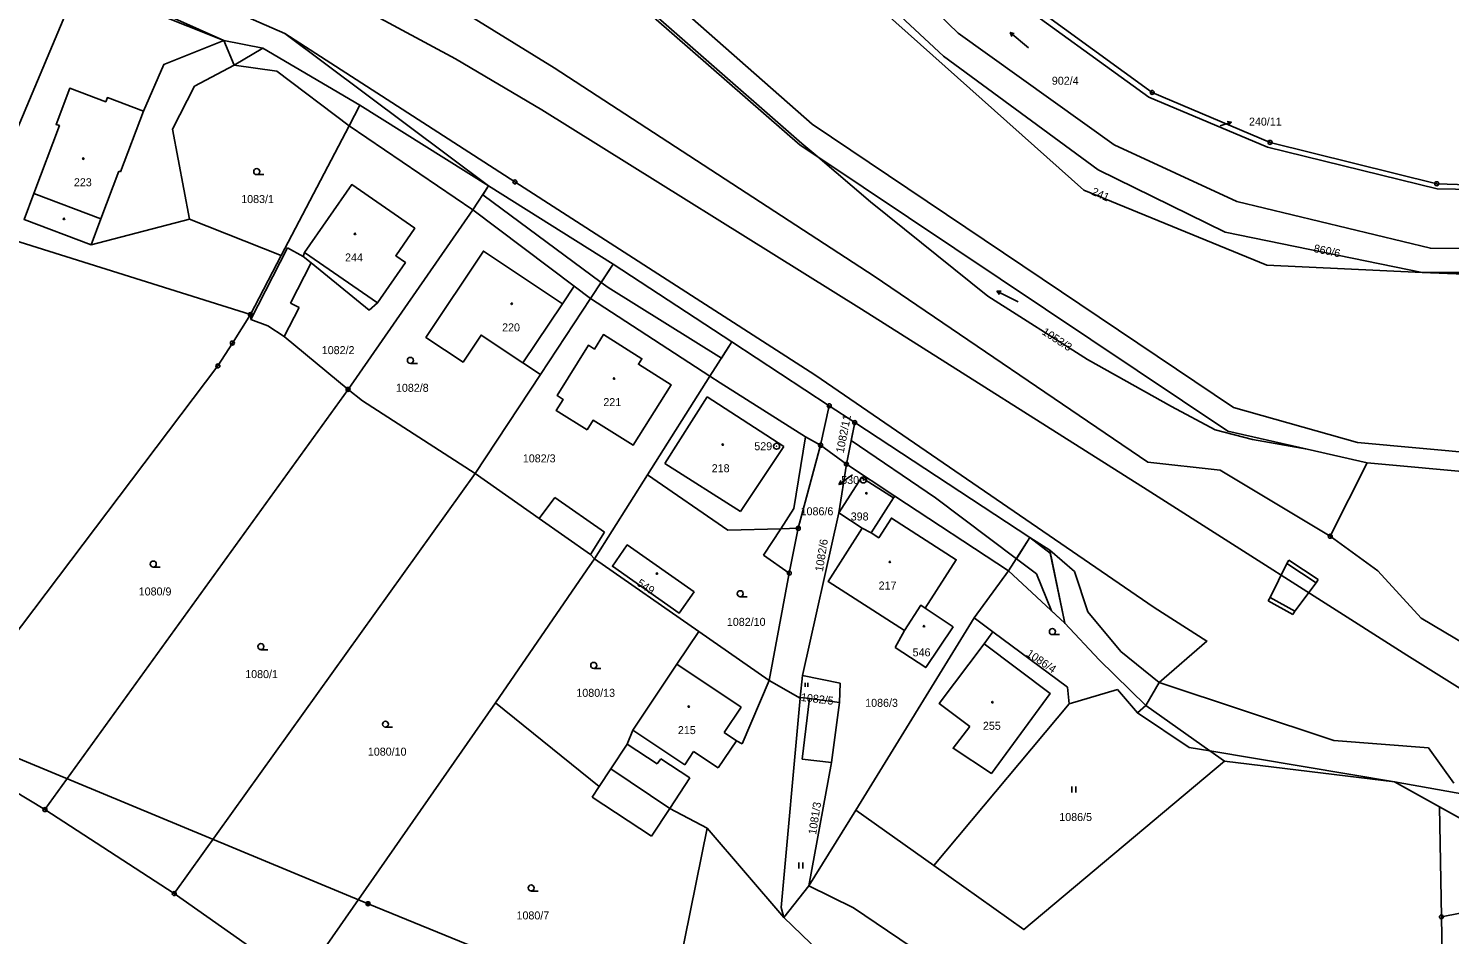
# Model space of a CAD drawing. Extents: x -745926 to -742978, y -968282 to -965689.
# Drawn here: x -744856.3 to -744678.7, y -967259 to -967145.7 of the extents above; entities that cross this region are included whole.
import ezdxf

# ---------------------------------------------------------------- set-up
doc = ezdxf.new("R2010")
doc.units = 0
for name, color, linetype in [('Hranice parcel', 7, 'Continuous'), ('Parcelní čísla', 7, 'Continuous'), ('Pop  PČ popisy', 7, 'Continuous'), ('Poz předměty', 7, 'Continuous'), ('Vnitřní kresba', 7, 'Continuous'), ('Věcná břemena k části', 7, 'Continuous'), ('Značky bodu BP', 7, 'Continuous'), ('Značky budov', 7, 'Continuous'), ('Značky kultur', 7, 'Continuous')]:
    doc.layers.add(name, color=color, linetype=linetype)

msp = doc.modelspace()

# ---------------------------------------------------------------- linework, layer by layer
at = {"layer": 'Hranice parcel'}
for p, q in [((-744862.95, -967170.69), (-744849.99, -967139.99)), ((-744849.99, -967139.99), (-744831.9, -967147.24)), ((-744826.99, -967148.18), (-744831.9, -967147.24)), ((-744814.88, -967155.32), (-744826.99, -967148.18)), ((-744798.8, -967165.4), (-744814.88, -967155.32)), ((-744757.65, -967161.79), (-744759.62, -967160.12)), ((-744783.22, -967175.19), (-744798.8, -967165.4)), ((-744828.56, -967181.48), (-744862.95, -967170.69)), ((-744783.22, -967175.19), (-744786.06, -967179.49)), ((-744768.4, -967184.9), (-744783.22, -967175.19)), ((-744643.72, -967176.24), (-744682.11, -967176.24)), ((-744658.4, -967177.18), (-744682.11, -967176.24)), ((-744792.32, -967188.99), (-744786.06, -967179.49)), ((-744830.81, -967185.04), (-744828.56, -967181.48)), ((-744832.63, -967187.9), (-744830.81, -967185.04)), ((-744756.21, -967192.89), (-744768.4, -967184.9)), ((-744868.17, -967234.92), (-744832.63, -967187.9)), ((-744792.32, -967188.99), (-744800.48, -967201.36)), ((-744816.36, -967190.83), (-744854.24, -967243.36)), ((-744757.29, -967197.82), (-744756.21, -967192.89)), ((-744756.21, -967192.89), (-744753.03, -967194.98)), ((-744753.03, -967194.98), (-744754.06, -967200.19)), ((-744731.13, -967209.33), (-744753.03, -967194.98)), ((-744760.08, -967208.2), (-744757.29, -967197.82)), ((-744754.06, -967200.19), (-744757.29, -967197.82)), ((-744689, -967200), (-744696.48, -967198.31)), ((-744689, -967200), (-744693.6, -967209.2)), ((-744838.08, -967253.85), (-744800.48, -967201.36)), ((-744785.57, -967212.01), (-744778.91, -967201.5)), ((-744755.02, -967206.28), (-744754.06, -967200.19)), ((-744750.99, -967208.76), (-744748.18, -967204.39)), ((-744759.57, -967226.6), (-744755.02, -967206.28)), ((-744755.02, -967206.28), (-744752.08, -967208.16)), ((-744750.99, -967208.76), (-744752.08, -967208.16)), ((-744728.66, -967210.94), (-744731.13, -967209.33)), ((-744772.53, -967221.09), (-744785.57, -967212.01)), ((-744744.22, -967218.17), (-744740.72, -967220.51)), ((-744763.73, -967227.22), (-744772.53, -967221.09)), ((-744747.96, -967223.11), (-744746.8, -967220.96)), ((-744716.65, -967230.33), (-744722.47, -967224.64)), ((-744759.57, -967226.6), (-744759.84, -967229.33)), ((-744759.86, -967229.43), (-744763.73, -967227.22)), ((-744797.92, -967229.99), (-744822.28, -967264.93)), ((-744759.84, -967229.33), (-744759.86, -967229.43)), ((-744854.24, -967243.36), (-744868.17, -967234.92)), ((-744706.83, -967237.32), (-744685.57, -967239.87)), ((-744685.57, -967239.87), (-744679.95, -967243.01)), ((-744854.24, -967243.36), (-744838.08, -967253.85)), ((-744752.9, -967243.41), (-744758.77, -967252.9)), ((-744743.14, -967250.35), (-744752.9, -967243.41)), ((-744679.95, -967243.01), (-744679.7, -967256.76)), ((-744777.66, -967276.07), (-744771.46, -967245.67)), ((-744771.46, -967245.67), (-744761.9, -967256.85)), ((-744758.77, -967252.9), (-744761.9, -967256.85)), ((-744822.28, -967264.93), (-744838.08, -967253.85))]:
    msp.add_line(p, q, dxfattribs=at)
for points in [[(-744693.6, -967209.2), (-744707.34, -967200.94), (-744716.41, -967199.92), (-744750.6, -967176.7), (-744790.58, -967150.66), (-744800.6, -967144.47), (-744829.49, -967128.26), (-744860.55, -967111.29), (-744889.69, -967099.44), (-744913.09, -967089.29)], [(-744949.24, -967094.01), (-744923.2, -967101.49), (-744908.83, -967109.73), (-744904.12, -967111.71), (-744867.87, -967127.34), (-744824.27, -967146.35), (-744795.5, -967164.9), (-744758, -967189), (-744715.6, -967218.1), (-744709, -967222.3), (-744714.96, -967227.46), (-744716.65, -967230.33)], [(-744831.9, -967147.24), (-744886.96, -967122.64), (-744909.4, -967113.93), (-744920.02, -967107.58), (-744947.9, -967099.97)], [(-744682.11, -967176.24), (-744706.73, -967171.2), (-744722.61, -967163.39), (-744741.92, -967149.18), (-744762.18, -967130.32), (-744771.51, -967120.53), (-744792.07, -967099.84)], [(-744792.07, -967099.84), (-744773.3, -967122.27), (-744724.39, -967165.93), (-744701.53, -967175.32), (-744682.11, -967176.24)], [(-744761.31, -967116.64), (-744753.2, -967122.59), (-744734.47, -967141.12), (-744716.27, -967154.3), (-744701.42, -967160.58), (-744680.25, -967165.77), (-744652.66, -967166.26), (-744623.32, -967164.11), (-744567.41, -967157.02), (-744564.47, -967157.4)], [(-744806.72, -967119.21), (-744782.44, -967140.57), (-744759.86, -967160.31), (-744757.65, -967161.79)], [(-744759.62, -967160.12), (-744785.56, -967137.39), (-744806.27, -967119.19)], [(-744752.98, -967122.18), (-744734.28, -967140.31), (-744715.85, -967153.73), (-744701.12, -967159.96), (-744680.29, -967165.13), (-744652.93, -967166.02), (-744624.12, -967163.47), (-744567.4, -967156.72)], [(-744758.97, -967128.01), (-744740.08, -967146.3), (-744720.61, -967160.28), (-744705.28, -967167.36), (-744681.07, -967173.2), (-744652.2, -967173.45), (-744630.58, -967172.14)], [(-744831.9, -967147.24), (-744839.39, -967150.22), (-744841.94, -967156.05), (-744846.44, -967154.36), (-744846.63, -967154.88), (-744851.14, -967153.19), (-744852.85, -967157.72), (-744852.43, -967157.87), (-744855.62, -967166.35), (-744856.85, -967169.61), (-744848.47, -967172.76), (-744836.16, -967169.58), (-744838.29, -967158.3), (-744835.56, -967152.95), (-744830.59, -967150.33), (-744826.99, -967148.18)], [(-744814.88, -967155.32), (-744816.22, -967157.89), (-744824.7, -967174.1), (-744828.56, -967181.48)], [(-744696.48, -967198.31), (-744703.32, -967197.09), (-744707.99, -967195.9), (-744713.45, -967192.99), (-744723.92, -967187.09), (-744736.41, -967179.17), (-744751.06, -967167.39), (-744757.65, -967161.79)], [(-744696.48, -967198.31), (-744706.4, -967196.07), (-744757.65, -967161.79)], [(-744813.73, -967180.92), (-744812.67, -967180.02), (-744809.18, -967174.98), (-744810.39, -967174.14), (-744808.01, -967170.69), (-744815.9, -967165.23), (-744821.78, -967173.72), (-744821.98, -967174.24), (-744820.97, -967175.03), (-744813.73, -967180.92)], [(-744816.36, -967190.83), (-744800.75, -967168.4), (-744798.8, -967165.4)], [(-744786.06, -967179.49), (-744788.1, -967177.95), (-744789.57, -967180.14), (-744799.44, -967173.56), (-744806.62, -967184.34), (-744801.98, -967187.43), (-744799.72, -967184.04), (-744794.49, -967187.52), (-744792.32, -967188.99)], [(-744816.36, -967190.83), (-744824.32, -967184.23), (-744826.37, -967182.9), (-744828.49, -967182.1), (-744828.56, -967181.48)], [(-744786.47, -967195.9), (-744785.72, -967194.7), (-744780.73, -967197.82), (-744775.99, -967190.26), (-744780.07, -967187.7), (-744779.63, -967187), (-744784.43, -967183.99), (-744785.56, -967185.8), (-744786.31, -967185.33), (-744790.24, -967191.6), (-744789.47, -967192.09), (-744790.34, -967193.48), (-744786.47, -967195.9)], [(-744768.4, -967184.9), (-744771.12, -967189.2), (-744778.91, -967201.5)], [(-744800.48, -967201.36), (-744814.56, -967192.27), (-744816.36, -967190.83)], [(-744617.81, -967196.99), (-744645.44, -967199.78), (-744674.83, -967201.29), (-744689, -967200)], [(-744785.57, -967212.01), (-744786.07, -967211.48), (-744792.46, -967206.98), (-744800.48, -967201.36)], [(-744778.91, -967201.5), (-744768.87, -967208.41), (-744762.27, -967208.26), (-744760.08, -967208.2)], [(-744748.18, -967204.39), (-744752.17, -967201.83), (-744755.02, -967206.28)], [(-744754.06, -967200.19), (-744748.01, -967204.17), (-744748.18, -967204.39)], [(-744744.22, -967218.17), (-744740.34, -967212.13), (-744748.45, -967206.93), (-744750.03, -967209.38), (-744750.99, -967208.76)], [(-744760.08, -967208.2), (-744761.21, -967213.8), (-744763.73, -967227.22)], [(-744752.08, -967208.16), (-744756.36, -967214.83), (-744746.8, -967220.96)], [(-744773.1, -967216.14), (-744774.96, -967218.79), (-744783.32, -967212.94), (-744781.46, -967210.28), (-744773.1, -967216.14)], [(-744752.9, -967243.41), (-744738.08, -967219.39), (-744733.79, -967213.53), (-744731.13, -967209.33)], [(-744654.82, -967235.73), (-744682.24, -967219.41), (-744687.64, -967213.53), (-744693.6, -967209.2)], [(-744797.92, -967229.99), (-744786.52, -967213.4), (-744785.57, -967212.01)], [(-744722.47, -967224.64), (-744726.77, -967220.07), (-744728.66, -967210.94)], [(-744746.8, -967220.96), (-744744.78, -967217.81), (-744744.22, -967218.17)], [(-744772.53, -967221.09), (-744775.26, -967225.16), (-744780.77, -967233.41), (-744781.46, -967235.16), (-744783.51, -967238.27)], [(-744740.72, -967220.51), (-744744.16, -967225.61), (-744747.96, -967223.11)], [(-744738.66, -967232.96), (-744740.73, -967235.69), (-744735.94, -967238.83), (-744728.62, -967228.84), (-744736.85, -967222.62), (-744742.48, -967230.08), (-744738.66, -967232.96)], [(-744754.94, -967229.97), (-744754.86, -967227.57), (-744759.57, -967226.6)], [(-744743.14, -967250.35), (-744726.24, -967230.14), (-744720.2, -967228.36), (-744717.69, -967231.25), (-744716.65, -967230.33)], [(-744783.51, -967238.27), (-744784.96, -967240.45), (-744797.92, -967229.99)], [(-744761.9, -967256.85), (-744762.21, -967255.57), (-744759.86, -967229.43)], [(-744754.94, -967229.97), (-744758.7, -967229.48), (-744759.84, -967229.33)], [(-744758.77, -967252.9), (-744755.92, -967237.48), (-744754.94, -967229.97)], [(-744716.65, -967230.33), (-744708.66, -967236.02), (-744706.83, -967237.32)], [(-744706.83, -967237.32), (-744731.9, -967258.34), (-744743.14, -967250.35)], [(-744783.51, -967238.27), (-744776.13, -967243.2), (-744771.46, -967245.67)], [(-744685.57, -967239.87), (-744674.82, -967241.79), (-744668.23, -967242.96), (-744659.62, -967250.35)], [(-744679.7, -967256.76), (-744670.98, -967255.03), (-744664.34, -967251.69), (-744660.58, -967250.82), (-744659.62, -967250.35)], [(-744738.76, -967274.28), (-744743.16, -967262.41), (-744753.18, -967255.64), (-744758.77, -967252.9)], [(-744749.3, -967268.65), (-744751.81, -967266.56), (-744761.9, -967256.85)], [(-744679.47, -967286.02), (-744679.22, -967283.47), (-744679.7, -967256.76)]]:
    msp.add_lwpolyline(points, dxfattribs=at)
at = {"layer": 'Pop  PČ popisy'}
for p, q in [((-744707.35, -967157.88), (-744705.92, -967157.44)), ((-744705.92, -967157.44), (-744706.47, -967157.35)), ((-744705.92, -967157.44), (-744706.32, -967157.83)), ((-744753.79, -967201.86), (-744755.02, -967202.72)), ((-744753.32, -967201.52), (-744753.79, -967201.86)), ((-744755.02, -967202.72), (-744754.75, -967202.23)), ((-744755.02, -967202.72), (-744754.47, -967202.64))]:
    msp.add_line(p, q, dxfattribs=at)
at = {"layer": 'Poz předměty'}
for p, q in [((-744832.7, -967133.45), (-744802.93, -967149.54)), ((-744802.93, -967149.54), (-744792.15, -967155.89)), ((-744792.15, -967155.89), (-744752.17, -967180.81)), ((-744752.17, -967180.81), (-744716.49, -967203.39)), ((-744716.49, -967203.39), (-744684.01, -967224.04)), ((-744684.01, -967224.04), (-744565.17, -967298.79)), ((-744866.49, -967233.28), (-744813.86, -967255.12)), ((-744813.86, -967255.12), (-744724.97, -967291.39))]:
    msp.add_line(p, q, dxfattribs=at)
for radius in [0.25, 0.2, 0.15, 0.1, 0.05]:
    msp.add_circle((-744813.86, -967255.12), radius, dxfattribs=at)
at = {"layer": 'Vnitřní kresba'}
for p, q in [((-744758.34, -967157.68), (-744781.15, -967137.61)), ((-744798.8, -967165.4), (-744824.27, -967146.35)), ((-744831.9, -967147.24), (-744830.59, -967150.33)), ((-744830.59, -967150.33), (-744825.24, -967151.06)), ((-744825.24, -967151.06), (-744816.22, -967157.89)), ((-744841.94, -967156.05), (-744844.8, -967163.63)), ((-744800.75, -967168.4), (-744816.22, -967157.89)), ((-744705.67, -967193.11), (-744758.34, -967157.68)), ((-744845.01, -967163.55), (-744847.25, -967169.5)), ((-744844.8, -967163.63), (-744845.01, -967163.55)), ((-744855.62, -967166.35), (-744847.25, -967169.5)), ((-744847.25, -967169.5), (-744848.47, -967172.76)), ((-744836.16, -967169.58), (-744824.7, -967174.1)), ((-744788.1, -967177.95), (-744800.75, -967168.4)), ((-744828.49, -967182.1), (-744823.91, -967173.15)), ((-744823.91, -967173.15), (-744821.98, -967174.24)), ((-744820.97, -967175.03), (-744823.54, -967180.06)), ((-744812.67, -967180.02), (-744821.78, -967173.72)), ((-744823.54, -967180.06), (-744822.46, -967180.61)), ((-744794.49, -967187.52), (-744789.57, -967180.14)), ((-744786.06, -967179.49), (-744771.12, -967189.2)), ((-744822.46, -967180.61), (-744824.32, -967184.23)), ((-744769.86, -967190.02), (-744771.12, -967189.2)), ((-744759.17, -967196.77), (-744769.86, -967190.02)), ((-744776.78, -967200.08), (-744771.49, -967191.75)), ((-744771.49, -967191.75), (-744761.87, -967197.99)), ((-744690.17, -967197.48), (-744705.67, -967193.11)), ((-744761.87, -967197.99), (-744767.32, -967206.08)), ((-744759.17, -967196.77), (-744760.63, -967205.72)), ((-744757.29, -967197.82), (-744759.17, -967196.77)), ((-744674.58, -967198.89), (-744690.17, -967197.48)), ((-744767.32, -967206.08), (-744776.78, -967200.08)), ((-744792.46, -967206.98), (-744790.53, -967204.35)), ((-744790.53, -967204.35), (-744784.31, -967208.69)), ((-744733.79, -967213.53), (-744748.01, -967204.17)), ((-744760.63, -967205.72), (-744762.27, -967208.26)), ((-744784.31, -967208.69), (-744786.07, -967211.48)), ((-744762.27, -967208.26), (-744764.41, -967211.55)), ((-744764.41, -967211.55), (-744761.21, -967213.8)), ((-744725.55, -967213.59), (-744728.66, -967210.94)), ((-744699.03, -967212.6), (-744698.76, -967212.18)), ((-744698.76, -967212.18), (-744695.09, -967214.61)), ((-744733.79, -967213.53), (-744726.77, -967220.07)), ((-744723.89, -967218.64), (-744725.55, -967213.59)), ((-744699.03, -967212.6), (-744701.11, -967216.83)), ((-744695.36, -967215.03), (-744699.03, -967212.6)), ((-744695.36, -967215.03), (-744698.03, -967218.54)), ((-744695.09, -967214.61), (-744695.36, -967215.03)), ((-744701.36, -967217.27), (-744701.11, -967216.83)), ((-744698.27, -967218.97), (-744701.36, -967217.27)), ((-744701.11, -967216.83), (-744698.03, -967218.54)), ((-744738.08, -967219.39), (-744735.75, -967221.12)), ((-744719.75, -967223.61), (-744723.89, -967218.64)), ((-744698.03, -967218.54), (-744698.27, -967218.97)), ((-744735.75, -967221.12), (-744736.85, -967222.62)), ((-744735.75, -967221.12), (-744726.44, -967228.06)), ((-744714.96, -967227.46), (-744719.75, -967223.61)), ((-744775.26, -967225.16), (-744767.21, -967230.54)), ((-744767.11, -967235.13), (-744763.73, -967227.22)), ((-744726.44, -967228.06), (-744726.24, -967230.14)), ((-744714.96, -967227.46), (-744693.15, -967234.73)), ((-744758.7, -967229.48), (-744759.6, -967237.07)), ((-744767.21, -967230.54), (-744769.35, -967233.73)), ((-744717.69, -967231.25), (-744711.23, -967235.59)), ((-744774.28, -967237.75), (-744780.77, -967233.41)), ((-744769.35, -967233.73), (-744767.82, -967234.75)), ((-744781.46, -967235.16), (-744777.7, -967237.65)), ((-744767.82, -967234.75), (-744770.08, -967238.13)), ((-744767.82, -967234.75), (-744767.11, -967235.13)), ((-744711.23, -967235.59), (-744708.66, -967236.02)), ((-744693.15, -967234.73), (-744681.32, -967235.65)), ((-744777.7, -967237.65), (-744777.27, -967236.99)), ((-744777.27, -967236.99), (-744773.62, -967239.4)), ((-744773.16, -967236.08), (-744774.28, -967237.75)), ((-744770.08, -967238.13), (-744773.16, -967236.08)), ((-744759.6, -967237.07), (-744755.92, -967237.48)), ((-744708.66, -967236.02), (-744685.57, -967239.87)), ((-744681.32, -967235.65), (-744678.14, -967240.05)), ((-744785.84, -967241.78), (-744784.96, -967240.45)), ((-744773.62, -967239.4), (-744776.13, -967243.2)), ((-744778.43, -967246.68), (-744785.84, -967241.78)), ((-744776.13, -967243.2), (-744778.43, -967246.68)), ((-744672.32, -967247.27), (-744679.95, -967243.01))]:
    msp.add_line(p, q, dxfattribs=at)
at = {"layer": 'Věcná břemena k části'}
for points in [[(-744799.53, -967166.52), (-744784.73, -967177.47), (-744783.22, -967175.19), (-744798.8, -967165.4)], [(-744784.73, -967177.47), (-744783.85, -967178.12), (-744769.68, -967186.93), (-744768.4, -967184.9), (-744783.22, -967175.19)], [(-744753.48, -967197.23), (-744742.92, -967204.38), (-744732.82, -967212), (-744731.13, -967209.33), (-744753.03, -967194.98)], [(-744732.82, -967212), (-744730.32, -967213.88), (-744728.44, -967218.52), (-744726.77, -967220.07), (-744728.59, -967211.3), (-744731.13, -967209.33)]]:
    msp.add_lwpolyline(points, close=True, dxfattribs=at)
at = {"layer": 'Značky bodu BP'}
for centre, radius in [((-744715.85, -967153.73), 0.25), ((-744715.85, -967153.73), 0.0152), ((-744701.12, -967159.96), 0.25), ((-744701.12, -967159.96), 0.0152), ((-744795.5, -967164.9), 0.25), ((-744795.5, -967164.9), 0.0152), ((-744680.29, -967165.13), 0.25), ((-744680.29, -967165.13), 0.0152), ((-744828.56, -967181.48), 0.25), ((-744828.56, -967181.48), 0.0152), ((-744830.81, -967185.04), 0.25), ((-744830.81, -967185.04), 0.0152), ((-744832.63, -967187.9), 0.25), ((-744832.63, -967187.9), 0.0152), ((-744816.36, -967190.83), 0.25), ((-744816.36, -967190.83), 0.0152), ((-744756.21, -967192.89), 0.25), ((-744756.21, -967192.89), 0.0152), ((-744753.03, -967194.98), 0.25), ((-744753.03, -967194.98), 0.0152), ((-744762.79, -967197.94), 0.375), ((-744762.79, -967197.94), 0.015), ((-744757.29, -967197.82), 0.25), ((-744757.29, -967197.82), 0.0152), ((-744754.06, -967200.19), 0.25), ((-744754.06, -967200.19), 0.0152), ((-744751.95, -967202.16), 0.375), ((-744751.95, -967202.16), 0.015), ((-744760.08, -967208.2), 0.25), ((-744760.08, -967208.2), 0.0152), ((-744693.6, -967209.2), 0.25), ((-744693.6, -967209.2), 0.0152), ((-744761.21, -967213.8), 0.25), ((-744761.21, -967213.8), 0.0152), ((-744854.24, -967243.36), 0.25), ((-744854.24, -967243.36), 0.0152), ((-744838.08, -967253.85), 0.25), ((-744838.08, -967253.85), 0.0152), ((-744679.7, -967256.76), 0.25), ((-744679.7, -967256.76), 0.0152)]:
    msp.add_circle(centre, radius, dxfattribs=at)
at = {"layer": 'Značky budov'}
for centre in [(-744849.45, -967162), (-744851.86, -967169.53), (-744815.49, -967171.4), (-744795.9, -967180.14), (-744783.1, -967189.48), (-744769.52, -967197.74), (-744751.57, -967203.82), (-744748.64, -967212.4), (-744777.75, -967213.86), (-744744.37, -967220.43), (-744735.81, -967229.93), (-744773.77, -967230.47)]:
    msp.add_circle(centre, 0.0875, dxfattribs=at)
at = {"layer": 'Značky kultur'}
for p, q in [((-744731.31, -967148.15), (-744733.61, -967146.22)), ((-744733.61, -967146.22), (-744733.4, -967146.72)), ((-744733.61, -967146.22), (-744733.08, -967146.34)), ((-744827.77, -967164), (-744826.89, -967164)), ((-744732.6, -967179.9), (-744735.27, -967178.54)), ((-744735.27, -967178.54), (-744734.95, -967178.99)), ((-744735.27, -967178.54), (-744734.72, -967178.54)), ((-744808.57, -967187.59), (-744807.69, -967187.59)), ((-744840.7, -967213.04), (-744839.82, -967213.04)), ((-744767.34, -967216.75), (-744766.46, -967216.75)), ((-744728.33, -967221.49), (-744727.45, -967221.49)), ((-744827.25, -967223.37), (-744826.37, -967223.37)), ((-744785.65, -967225.71), (-744784.77, -967225.71)), ((-744759.21, -967228.02), (-744759.21, -967227.52)), ((-744758.88, -967228.02), (-744758.88, -967227.52)), ((-744811.68, -967233.06), (-744810.8, -967233.06)), ((-744725.91, -967241.23), (-744725.91, -967240.48)), ((-744725.41, -967241.23), (-744725.41, -967240.48)), ((-744760.02, -967250.71), (-744760.02, -967249.96)), ((-744759.52, -967250.71), (-744759.52, -967249.96)), ((-744793.47, -967253.53), (-744792.59, -967253.53))]:
    msp.add_line(p, q, dxfattribs=at)
for centre in [(-744827.77, -967163.62), (-744808.57, -967187.21), (-744840.7, -967212.66), (-744767.34, -967216.37), (-744728.33, -967221.11), (-744827.25, -967222.99), (-744785.65, -967225.33), (-744811.68, -967232.68), (-744793.47, -967253.15)]:
    msp.add_circle(centre, 0.375, dxfattribs=at)

# ---------------------------------------------------------------- texts
at = {"layer": 'Parcelní čísla'}
for s, p in [('902/4', (-744728.39, -967152.76)), ('240/11', (-744703.75, -967157.87)), ('223', (-744850.62, -967165.45)), ('1083/1', (-744829.71, -967167.55)), ('244', (-744816.73, -967174.85)), ('220', (-744797.1, -967183.59)), ('1082/2', (-744819.64, -967186.43)), ('1082/8', (-744810.37, -967191.14)), ('221', (-744784.45, -967192.93)), ('1082/3', (-744794.51, -967199.96)), ('218', (-744770.9, -967201.19)), ('1086/6', (-744759.79, -967206.57)), ('398', (-744753.53, -967207.22)), ('1080/9', (-744842.52, -967216.59)), ('217', (-744750.04, -967215.85)), ('1082/10', (-744769.01, -967220.39)), ('546', (-744745.79, -967224.2)), ('1080/1', (-744829.21, -967226.92)), ('1080/13', (-744787.82, -967229.26)), ('1086/3', (-744751.72, -967230.51)), ('215', (-744775.13, -967233.92)), ('255', (-744737.01, -967233.38)), ('1080/10', (-744813.88, -967236.61)), ('1086/5', (-744727.46, -967244.78)), ('1080/7', (-744795.3, -967257.08))]:
    msp.add_text(s, height=1, dxfattribs=at).set_placement(p)
for s, rotation, p in [('241', 336, (-744723.52, -967166.46)), ('860/6', 348, (-744695.73, -967173.66)), ('1053/3', 327, (-744729.71, -967183.88)), ('1082/11', 79, (-744754.41, -967198.85)), ('1082/6', 81, (-744757.01, -967213.67)), ('549', 327, (-744780.33, -967215.29)), ('1086/4', 326, (-744731.67, -967224.07)), ('1082/5', 353, (-744759.8, -967229.77)), ('1081/3', 81, (-744757.86, -967246.53))]:
    msp.add_text(s, height=1, rotation=rotation, dxfattribs=at).set_placement(p)
at = {"layer": 'Značky bodu BP'}
for s, p in [('529', (-744765.58, -967198.44)), ('530', (-744754.72, -967202.66))]:
    msp.add_text(s, height=1, dxfattribs=at).set_placement(p)

doc.saveas('drawing.dxf')
